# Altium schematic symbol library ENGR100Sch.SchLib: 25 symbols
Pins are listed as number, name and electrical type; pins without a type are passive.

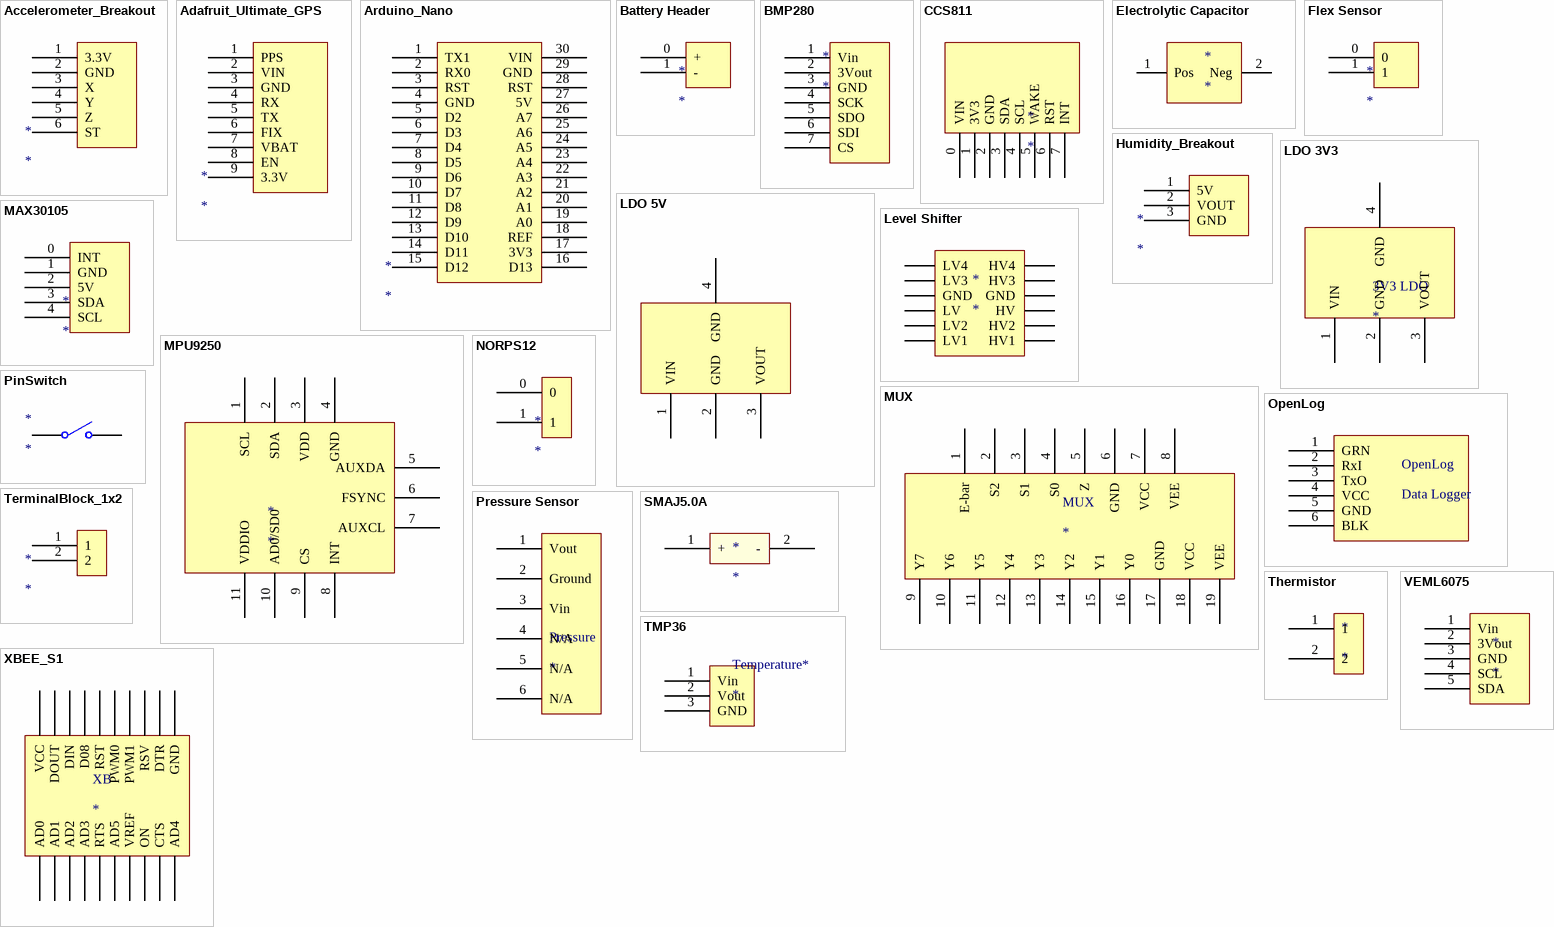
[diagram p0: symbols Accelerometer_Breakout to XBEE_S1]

## Accelerometer_Breakout
designator *
ADXL335 3-axis accelerometer
footprint Accelerometer_Breakout
pins: 1 3.3V, 2 GND, 3 X, 4 Y, 5 Z, 6 ST

## Adafruit_Ultimate_GPS
designator *
UART GPS module from adafruit
footprint Adafruit_Ultimate_GPS (Adafruit GPS Breakout Board)
pins: 1 PPS, 2 VIN, 3 GND, 4 RX, 5 TX, 6 FIX, 7 VBAT, 8 EN, 9 3.3V

## Arduino_Nano
designator *
Arduino Nano board
footprint Arduino_Nano
pins: 1 TX1, 2 RX0, 3 RST, 4 GND, 5 D2, 6 D3, 7 D4, 8 D5, 9 D6, 10 D7, 11 D8, 12 D9, 13 D10, 14 D11, 15 D12, 16 D13, 17 3V3, 18 REF, 19 A0, 20 A1, 21 A2, 22 A3, 23 A4, 24 A5, 25 A6, 26 A7, 27 5V, 28 RST, 29 GND, 30 VIN

## Battery Header
designator *
footprint Battery Header (Spring Terminal Battery Header)
pins: 0 +, 1 -

## BMP280
designator *
BMP280 Pressure, Altitude, and Temperature Sensor
footprint BMP280
pins: 1 Vin, 2 3Vout, 3 GND, 4 SCK, 5 SDO, 6 SDI, 7 CS

## CCS811
designator *
footprint CCS811 (Air Quality Sensor)
pins: 0 VIN, 1 3V3, 2 GND, 3 SDA, 4 SCL, 5 WAKE, 6 RST, 7 INT

## Electrolytic Capacitor
designator *
Filter Capacitor
footprint Electrolytic Capacitor
footprint Electrolytic Capacitor
pins: 1 Pos, 2 Neg

## Flex Sensor
designator *
footprint Flex Sensor (Long and Short Flex Sensor)
pins: 0, 1

## Humidity_Breakout
designator *
HIH4030 Humidity Sensor Breakout
footprint Humidity_Breakout
pins: 1 5V, 2 VOUT, 3 GND

## LDO 3V3
designator 3V3 LDO
UA78M05 LDO
footprint SOT223-4N (SOT223, 4-Leads, Body 6.5x3.5mm, Pitch 2.3mm, Lead Span 7mm, IPC Medium Density)
pins: 1 VIN, 2 GND, 3 VOUT, 4 GND

## LDO 5V
designator U?, comment LM340
LM340 LDO 5V Out
footprint SOT223-4N (SOT223, 4-Leads, Body 6.5x3.5mm, Pitch 2.3mm, Lead Span 7mm, IPC Medium Density)
pins: 1 VIN, 2 GND, 3 VOUT, 4 GND

## Level Shifter
designator *
Logic Level Shifter from Sparkfun
footprint Level Shifter (1X06)
pins: 1 LV4, 2 LV3, 3 GND, 4 LV, 5 LV2, 6 LV1, 7 HV4, 8 HV3, 9 GND, 10 HV, 11 HV2, 12 HV1

## MAX30105
designator *
footprint MAX30105 (Particle Sensor)
pins: 0 INT, 1 GND, 2 5V, 3 SDA, 4 SCL

## MPU9250
designator *
MPU9250 9-axis IMU from Sparkfun
footprint MPU9250 (IMU from sparkfun)
pins: 1 SCL, 2 SDA, 3 VDD, 4 GND, 5 AUXDA, 6 FSYNC, 7 AUXCL, 8 INT, 9 CS, 10 AD0/SD0, 11 VDDIO

## MUX
designator MUX
8-to-1 MUX 74HC4051 from Sparkfun
footprint MUX (74HC4051 from Sparkfun)
pins: 1 E-bar, 2 S2, 3 S1, 4 S0, 5 Z, 6 GND, 7 VCC, 8 VEE, 9 Y7, 10 Y6, 11 Y5, 12 Y4, 13 Y3, 14 Y2, 15 Y1, 16 Y0, 17 GND, 18 VCC, 19 VEE

## NORPS12
designator *
footprint NORPS12 (NORPS-12 Photocell)
pins: 0, 1

## OpenLog
designator OpenLog, comment Data Logger
footprint OpenLog
pins: 1 GRN "OpenLog", 2 RxI "OpenLog", 3 TxO "OpenLog", 4 VCC "OpenLog", 5 GND "OpenLog", 6 BLK "OpenLog"

## PinSwitch
designator *
RBF pin for turning on/off payload
footprint SwitchPin
pins: 0 COMMON, 1 NO

## Pressure Sensor
designator Pressure
MPX4115A Pressure Sensor
footprint Pressure Sensor (MPX4115A)
pins: 1 Vout, 2 Ground, 3 Vin, 4 N/A, 5 N/A, 6 N/A

## SMAJ5.0A
designator *
Circuit Protection Diode
footprint SMAJ5.0A
pins: 1 +, 2 -

## TerminalBlock_1x2
designator *
Battery input and stability
pins: 1, 2

## Thermistor
designator *
Nonlinear Temperature Sensor 1k ohms room temperature
footprint Thermistor
pins: 1, 2

## TMP36
designator Temperature*
A temperature sensor for ENGR100 TMP36 model
footprint TMP36 (TMP36 Temperature Sensor)
pins: 1 Vin, 2 Vout, 3 GND

## VEML6075
designator *
VEML6075 UV Light sensor from adafruit
footprint VEML6075 (UV-light sensor module from adafruit)
pins: 1 Vin, 2 3Vout, 3 GND, 4 SCL, 5 SDA

## XBEE_S1
designator XB
XBee RF module
footprint XBEE_S1 (XBee S1 Footprint STD)
pins: 1 VCC, 2 DOUT, 3 DIN, 4 D08, 5 RST, 6 PWM0, 7 PWM1, 8 RSV, 9 DTR, 10 GND, 11 AD4, 12 CTS, 13 ON, 14 VREF, 15 AD5, 16 RTS, 17 AD3, 18 AD2, 19 AD1, 20 AD0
